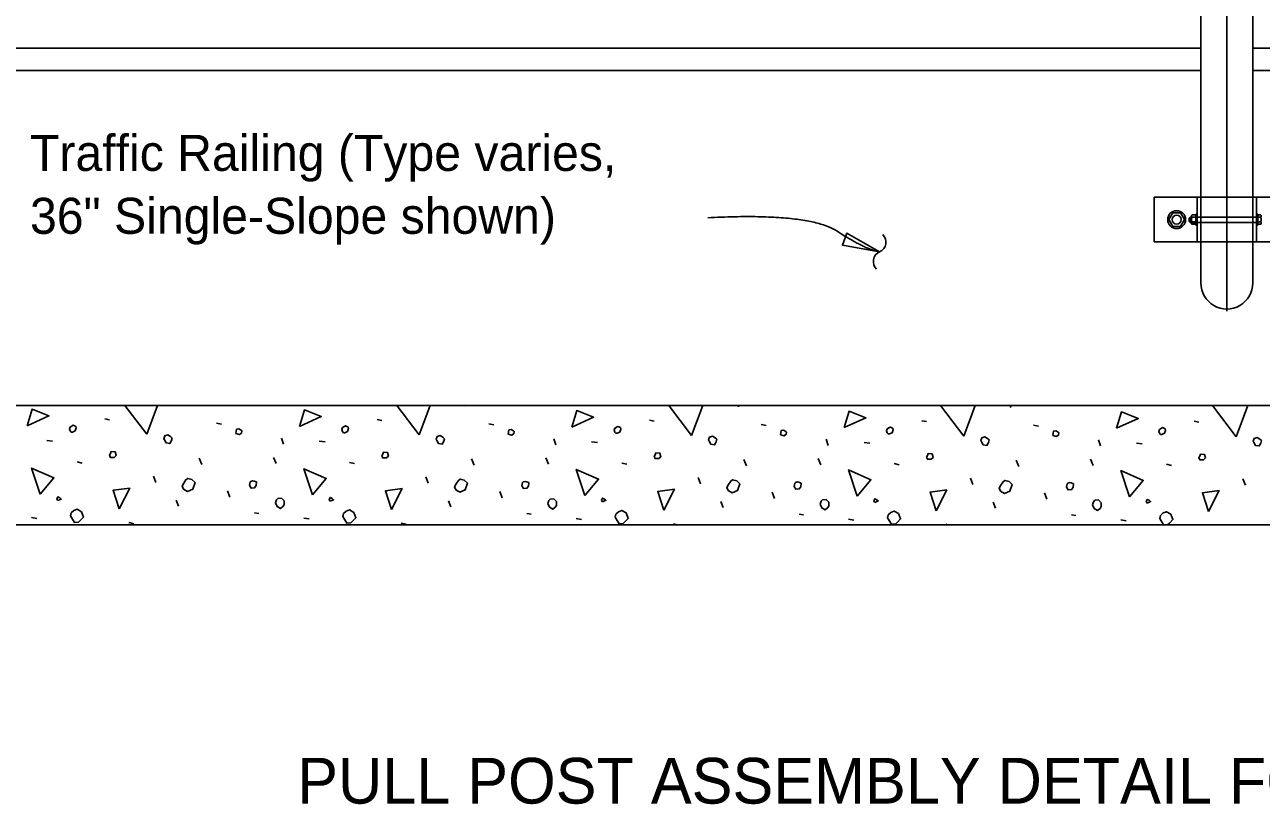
# Model space of a CAD drawing. Extents: x 0 to 72.1, y -7 to 30.
# Drawn here: x 5.5 to 12.41, y 13.96 to 18.32 of the extents above; entities that cross this region are included whole.
import ezdxf

# ---------------------------------------------------------------- set-up
doc = ezdxf.new("R2010")
doc.units = 0
for name, color, linetype in [('AdhocPoint_dp', 7, 'Continuous'), ('Border', 7, 'Continuous'), ('Patterning', 7, 'Continuous'), ('PlotBorder_dp', 7, 'Continuous'), ('SheetBorder_dp', 7, 'Continuous'), ('TextMisc', 7, 'Continuous'), ('TextStructures', 7, 'Continuous')]:
    doc.layers.add(name, color=color, linetype=linetype)

msp = doc.modelspace()

# ---------------------------------------------------------------- linework, layer by layer
at = {"layer": 'AdhocPoint_dp'}
for p, q in [((12.0147, 17.2229), (12.0147, 17.235)), ((12.0204, 17.2229), (12.0204, 17.235)), ((7.9664, 16.1864), (7.9651, 16.1899)), ((9.4903, 16.1829), (9.4877, 16.1899)), ((11.0141, 16.1793), (11.0102, 16.1899)), ((5.9441, 16.1157), (5.9706, 16.1104)), ((6.5699, 16.0909), (6.5964, 16.0856)), ((7.4679, 16.1122), (7.4945, 16.1068)), ((8.0937, 16.0874), (8.1202, 16.0821)), ((8.9918, 16.1086), (9.0183, 16.1033)), ((9.6175, 16.0839), (9.6441, 16.0786)), ((10.5156, 16.1051), (10.5421, 16.0998)), ((11.1414, 16.0803), (11.1679, 16.075)), ((12.0394, 16.1015), (12.0659, 16.0962)), ((5.6206, 15.9937), (5.6524, 15.9902)), ((6.9447, 15.9743), (6.9323, 16.0079)), ((7.1444, 15.9902), (7.1763, 15.9866)), ((8.4685, 15.9707), (8.4561, 16.0043)), ((8.6683, 15.9866), (8.7001, 15.9831)), ((9.9923, 15.9672), (9.9799, 16.0008)), ((10.1921, 15.9831), (10.2239, 15.9796)), ((11.5161, 15.9637), (11.5038, 15.9972)), ((11.7159, 15.9796), (11.7477, 15.976)), ((5.7886, 15.8753), (5.8168, 15.8682)), ((6.4868, 15.8594), (6.4727, 15.8947)), ((6.9023, 15.8647), (6.8881, 15.9)), ((7.3124, 15.8717), (7.3407, 15.8647)), ((8.0106, 15.8558), (7.9965, 15.8912)), ((8.4261, 15.8611), (8.4119, 15.8965)), ((8.8362, 15.8682), (8.8645, 15.8611)), ((9.5345, 15.8523), (9.5203, 15.8876)), ((9.9499, 15.8576), (9.9357, 15.8929)), ((10.36, 15.8647), (10.3883, 15.8576)), ((11.0583, 15.8488), (11.0441, 15.8841)), ((11.4737, 15.8541), (11.4596, 15.8894)), ((11.8838, 15.8611), (11.9121, 15.8541)), ((6.2305, 15.7586), (6.2164, 15.794)), ((7.7543, 15.7551), (7.7402, 15.7904)), ((9.2781, 15.7515), (9.264, 15.7869)), ((10.8019, 15.748), (10.7878, 15.7833)), ((12.3258, 15.7445), (12.3116, 15.7798)), ((6.6442, 15.6773), (6.63, 15.7126)), ((8.168, 15.6737), (8.1538, 15.7091)), ((6.356, 15.626), (6.3436, 15.6596)), ((7.8798, 15.6225), (7.8675, 15.6561)), ((9.4036, 15.6189), (9.3913, 15.6525)), ((9.6918, 15.6702), (9.6776, 15.7056)), ((10.9275, 15.6154), (10.9151, 15.649)), ((11.2156, 15.6667), (11.2015, 15.702)), ((6.782, 15.5889), (6.8068, 15.5854)), ((8.3059, 15.5854), (8.3306, 15.5818)), ((9.8297, 15.5818), (9.8544, 15.5783)), ((11.3535, 15.5783), (11.3782, 15.5748)), ((5.534, 15.5641), (5.5641, 15.5588)), ((6.0785, 15.5359), (6.1068, 15.5288)), ((7.0578, 15.5606), (7.0879, 15.5553)), ((7.6023, 15.5323), (7.6306, 15.5253)), ((8.5816, 15.5571), (8.6117, 15.5518)), ((9.1261, 15.5288), (9.1482, 15.5233)), ((10.1054, 15.5535), (10.1355, 15.5482)), ((10.6499, 15.5253), (10.6579, 15.5233)), ((11.6293, 15.55), (11.6593, 15.5447))]:
    msp.add_line(p, q, dxfattribs=at)
for points in [[(5.5093, 16.0768), (5.5375, 16.1687), (5.6312, 16.1316), (5.5093, 16.0768)], [(6.1792, 16.0291), (6.057, 16.1899)], [(6.2394, 16.1899), (6.1792, 16.0291)], [(7.0331, 16.0733), (7.0614, 16.1652), (7.155, 16.1281), (7.0331, 16.0733)], [(7.7031, 16.0255), (7.5781, 16.1899)], [(7.7645, 16.1899), (7.7031, 16.0255)], [(8.5569, 16.0697), (8.5852, 16.1617), (8.6789, 16.1245), (8.5569, 16.0697)], [(9.2269, 16.022), (9.0992, 16.1899)], [(9.2896, 16.1899), (9.2269, 16.022)], [(10.0807, 16.0662), (10.109, 16.1581), (10.2027, 16.121), (10.0807, 16.0662)], [(10.7507, 16.0185), (10.6204, 16.1899)], [(10.8148, 16.1899), (10.7507, 16.0185)], [(11.6045, 16.0627), (11.6328, 16.1546), (11.7265, 16.1175), (11.6045, 16.0627)], [(12.2745, 16.0149), (12.1415, 16.1899)], [(12.3399, 16.1899), (12.2745, 16.0149)], [(5.7567, 16.0414), (5.7638, 16.0414), (5.778, 16.0485), (5.7833, 16.0644), (5.7815, 16.0733), (5.7673, 16.0803), (5.7497, 16.0697), (5.7461, 16.0591), (5.7497, 16.0485), (5.7567, 16.0414)], [(6.6777, 16.0326), (6.6972, 16.0273), (6.7096, 16.0361), (6.7113, 16.0485), (6.7078, 16.052), (6.6937, 16.0591), (6.6813, 16.0574), (6.6795, 16.045), (6.6777, 16.0326)], [(7.2806, 16.0379), (7.2876, 16.0379), (7.3018, 16.045), (7.3071, 16.0609), (7.3053, 16.0697), (7.2912, 16.0768), (7.2735, 16.0662), (7.2699, 16.0556), (7.2735, 16.045), (7.2806, 16.0379)], [(8.2016, 16.0291), (8.221, 16.0238), (8.2334, 16.0326), (8.2351, 16.045), (8.2316, 16.0485), (8.2175, 16.0556), (8.2051, 16.0538), (8.2033, 16.0414), (8.2016, 16.0291)], [(8.8044, 16.0344), (8.8114, 16.0344), (8.8256, 16.0414), (8.8309, 16.0574), (8.8291, 16.0662), (8.815, 16.0733), (8.7973, 16.0627), (8.7938, 16.052), (8.7973, 16.0414), (8.8044, 16.0344)], [(9.7254, 16.0255), (9.7448, 16.0202), (9.7572, 16.0291), (9.759, 16.0414), (9.7554, 16.045), (9.7413, 16.052), (9.7289, 16.0503), (9.7271, 16.0379), (9.7254, 16.0255)], [(10.3282, 16.0308), (10.3353, 16.0308), (10.3494, 16.0379), (10.3547, 16.0538), (10.3529, 16.0627), (10.3388, 16.0697), (10.3211, 16.0591), (10.3176, 16.0485), (10.3211, 16.0379), (10.3282, 16.0308)], [(11.852, 16.0273), (11.8591, 16.0273), (11.8732, 16.0344), (11.8785, 16.0503), (11.8767, 16.0591), (11.8626, 16.0662), (11.8449, 16.0556), (11.8414, 16.045), (11.8449, 16.0344), (11.852, 16.0273)], [(6.2782, 15.9972), (6.2871, 15.9813), (6.3083, 15.9778), (6.3171, 15.9937), (6.3207, 16.0079), (6.3118, 16.0167), (6.2959, 16.0255), (6.28, 16.0202), (6.2747, 16.0043), (6.2782, 15.9972)], [(7.802, 15.9937), (7.8109, 15.9778), (7.8321, 15.9743), (7.8409, 15.9902), (7.8445, 16.0043), (7.8356, 16.0132), (7.8197, 16.022), (7.8038, 16.0167), (7.7985, 16.0008), (7.802, 15.9937)], [(9.3259, 15.9902), (9.3347, 15.9743), (9.3559, 15.9707), (9.3648, 15.9866), (9.3683, 16.0008), (9.3594, 16.0096), (9.3435, 16.0185), (9.3276, 16.0132), (9.3223, 15.9972), (9.3259, 15.9902)], [(10.8497, 15.9866), (10.8585, 15.9707), (10.8797, 15.9672), (10.8886, 15.9831), (10.8921, 15.9972), (10.8833, 16.0061), (10.8674, 16.0149), (10.8514, 16.0096), (10.8461, 15.9937), (10.8497, 15.9866)], [(11.2492, 16.022), (11.2686, 16.0167), (11.281, 16.0255), (11.2828, 16.0379), (11.2792, 16.0414), (11.2651, 16.0485), (11.2527, 16.0467), (11.251, 16.0344), (11.2492, 16.022)], [(12.3735, 15.9831), (12.3823, 15.9672), (12.4035, 15.9637), (12.4124, 15.9796), (12.4159, 15.9937), (12.4071, 16.0026), (12.3912, 16.0114), (12.3753, 16.0061), (12.37, 15.9902), (12.3735, 15.9831)], [(5.9759, 15.9), (5.9972, 15.9), (6.0078, 15.9106), (6.0025, 15.9301), (5.9795, 15.9318), (5.9759, 15.9212), (5.9706, 15.9124), (5.9759, 15.9), (5.9724, 15.9036)], [(7.4998, 15.8965), (7.521, 15.8965), (7.5316, 15.9071), (7.5263, 15.9265), (7.5033, 15.9283), (7.4998, 15.9177), (7.4945, 15.9089), (7.4998, 15.8965), (7.4962, 15.9)], [(9.0236, 15.8929), (9.0448, 15.8929), (9.0554, 15.9036), (9.0501, 15.923), (9.0271, 15.9248), (9.0236, 15.9142), (9.0183, 15.9053), (9.0236, 15.8929), (9.02, 15.8965)], [(10.5474, 15.8894), (10.5686, 15.8894), (10.5792, 15.9), (10.5739, 15.9195), (10.5509, 15.9212), (10.5474, 15.9106), (10.5421, 15.9018), (10.5474, 15.8894), (10.5439, 15.8929)], [(12.0712, 15.8859), (12.0924, 15.8859), (12.103, 15.8965), (12.0977, 15.9159), (12.0747, 15.9177), (12.0712, 15.9071), (12.0659, 15.8983), (12.0712, 15.8859), (12.0677, 15.8894)], [(5.5817, 15.6932), (5.534, 15.8399), (5.6595, 15.7851), (5.5817, 15.6932)], [(6.3843, 15.7215), (6.4073, 15.7091), (6.4373, 15.7215), (6.4497, 15.7586), (6.432, 15.7763), (6.409, 15.7816), (6.3984, 15.7745), (6.3861, 15.7551), (6.3772, 15.7392), (6.3843, 15.7215)], [(7.1055, 15.6897), (7.0578, 15.8364), (7.1833, 15.7816), (7.1055, 15.6897)], [(7.9081, 15.7179), (7.9311, 15.7056), (7.9611, 15.7179), (7.9735, 15.7551), (7.9558, 15.7727), (7.9329, 15.778), (7.9223, 15.771), (7.9099, 15.7515), (7.901, 15.7356), (7.9081, 15.7179)], [(8.6294, 15.6861), (8.5816, 15.8328), (8.7071, 15.778), (8.6294, 15.6861)], [(10.1532, 15.6826), (10.1054, 15.8293), (10.231, 15.7745), (10.1532, 15.6826)], [(11.677, 15.679), (11.6293, 15.8258), (11.7548, 15.771), (11.677, 15.679)], [(6.0237, 15.6119), (5.9901, 15.7162), (6.0838, 15.7285), (6.0237, 15.6119)], [(6.7538, 15.7445), (6.7626, 15.7285), (6.782, 15.7303), (6.7909, 15.7427), (6.7927, 15.7621), (6.7803, 15.7674), (6.7714, 15.7692), (6.7608, 15.7657), (6.7573, 15.7621), (6.7538, 15.7445)], [(7.5475, 15.6083), (7.5139, 15.7126), (7.6076, 15.725), (7.5475, 15.6083)], [(8.2776, 15.7409), (8.2864, 15.725), (8.3059, 15.7268), (8.3147, 15.7392), (8.3165, 15.7586), (8.3041, 15.7639), (8.2953, 15.7657), (8.2846, 15.7621), (8.2811, 15.7586), (8.2776, 15.7409)], [(9.0713, 15.6048), (9.0377, 15.7091), (9.1314, 15.7215), (9.0713, 15.6048)], [(9.4319, 15.7144), (9.4549, 15.702), (9.485, 15.7144), (9.4973, 15.7515), (9.4797, 15.7692), (9.4567, 15.7745), (9.4461, 15.7674), (9.4337, 15.748), (9.4249, 15.7321), (9.4319, 15.7144)], [(9.8014, 15.7374), (9.8102, 15.7215), (9.8297, 15.7232), (9.8385, 15.7356), (9.8403, 15.7551), (9.8279, 15.7604), (9.8191, 15.7621), (9.8085, 15.7586), (9.8049, 15.7551), (9.8014, 15.7374)], [(10.5951, 15.6013), (10.5615, 15.7056), (10.6552, 15.7179), (10.5951, 15.6013)], [(10.9557, 15.7109), (10.9787, 15.6985), (11.0088, 15.7109), (11.0211, 15.748), (11.0035, 15.7657), (10.9805, 15.771), (10.9699, 15.7639), (10.9575, 15.7445), (10.9487, 15.7285), (10.9557, 15.7109)], [(11.3252, 15.7339), (11.334, 15.7179), (11.3535, 15.7197), (11.3623, 15.7321), (11.3641, 15.7515), (11.3517, 15.7568), (11.3429, 15.7586), (11.3323, 15.7551), (11.3287, 15.7515), (11.3252, 15.7339)], [(12.1189, 15.5977), (12.0853, 15.702), (12.179, 15.7144), (12.1189, 15.5977)], [(5.6807, 15.6578), (5.7002, 15.6667), (5.6931, 15.6737), (5.6807, 15.679), (5.6754, 15.6667), (5.6807, 15.6578)], [(6.8987, 15.6455), (6.9093, 15.6242), (6.927, 15.6136), (6.9411, 15.6242), (6.9482, 15.6349), (6.9482, 15.6561), (6.9323, 15.672), (6.9129, 15.6702), (6.904, 15.6614), (6.8987, 15.6455)], [(7.2045, 15.6543), (7.224, 15.6631), (7.2169, 15.6702), (7.2045, 15.6755), (7.1992, 15.6631), (7.2045, 15.6543)], [(8.4225, 15.6419), (8.4331, 15.6207), (8.4508, 15.6101), (8.465, 15.6207), (8.472, 15.6313), (8.472, 15.6525), (8.4561, 15.6684), (8.4367, 15.6667), (8.4278, 15.6578), (8.4225, 15.6419)], [(8.7284, 15.6508), (8.7478, 15.6596), (8.7407, 15.6667), (8.7284, 15.672), (8.7231, 15.6596), (8.7284, 15.6508)], [(9.9463, 15.6384), (9.957, 15.6172), (9.9746, 15.6066), (9.9888, 15.6172), (9.9958, 15.6278), (9.9958, 15.649), (9.9799, 15.6649), (9.9605, 15.6631), (9.9517, 15.6543), (9.9463, 15.6384)], [(10.2522, 15.6472), (10.2716, 15.6561), (10.2645, 15.6631), (10.2522, 15.6684), (10.2469, 15.6561), (10.2522, 15.6472)], [(11.4702, 15.6349), (11.4808, 15.6136), (11.4984, 15.603), (11.5126, 15.6136), (11.5197, 15.6242), (11.5197, 15.6455), (11.5038, 15.6614), (11.4843, 15.6596), (11.4755, 15.6508), (11.4702, 15.6349)], [(11.776, 15.6437), (11.7954, 15.6525), (11.7884, 15.6596), (11.776, 15.6649), (11.7707, 15.6525), (11.776, 15.6437)], [(5.7514, 15.573), (5.7744, 15.5359), (5.7974, 15.5376), (5.8062, 15.5465), (5.8257, 15.5659), (5.8133, 15.596), (5.7886, 15.6101), (5.7709, 15.603), (5.7567, 15.5889), (5.7514, 15.573)], [(7.2753, 15.5694), (7.2982, 15.5323), (7.3212, 15.5341), (7.3301, 15.5429), (7.3495, 15.5624), (7.3371, 15.5924), (7.3124, 15.6066), (7.2947, 15.5995), (7.2806, 15.5854), (7.2753, 15.5694)], [(8.7991, 15.5659), (8.822, 15.5288), (8.845, 15.5306), (8.8539, 15.5394), (8.8733, 15.5588), (8.8609, 15.5889), (8.8362, 15.603), (8.8185, 15.596), (8.8044, 15.5818), (8.7991, 15.5659)], [(10.3229, 15.5624), (10.3459, 15.5253), (10.3688, 15.527), (10.3777, 15.5359), (10.3971, 15.5553), (10.3848, 15.5854), (10.36, 15.5995), (10.3423, 15.5924), (10.3282, 15.5783), (10.3229, 15.5624)], [(11.8898, 15.5233), (11.8927, 15.5235), (11.9015, 15.5323), (11.9209, 15.5518), (11.9086, 15.5818), (11.8838, 15.596), (11.8661, 15.5889), (11.852, 15.5748), (11.8467, 15.5588)], [(6.5728, 15.5233), (6.5717, 15.5235), (6.5702, 15.5233)], [(11.8467, 15.5588), (11.8687, 15.5233)]]:
    msp.add_lwpolyline(points, dxfattribs=at)
at = {"layer": 'Border'}
msp.add_lwpolyline([(10.2794, 17.0491), (10.0958, 17.1535), (10.0717, 17.0873)], close=True, dxfattribs=at)
for centre, start, end in [((10.2552, 17.1041), 294.14658, 45.87379), ((10.304, 16.9954), 114.14657, 225.87379)]:
    msp.add_arc(centre, 0.0596, start, end, dxfattribs=at)
msp.add_open_spline([(9.3188, 17.2407), (9.8816, 17.2691), (10.203, 17.0609), (10.2796, 17.0497)], degree=2, dxfattribs=at)
at = {"layer": 'Patterning'}
for p, q in [((12.0764, 17.3548), (12.0764, 17.1048)), ((12.3681, 17.3548), (12.3681, 17.1048)), ((12.3889, 17.2444), (12.024, 17.2444)), ((12.024, 17.2145), (12.3889, 17.2145))]:
    msp.add_line(p, q, dxfattribs=at)
at = {"layer": 'PlotBorder_dp'}
for p, q in [((12.0764, 18.6048), (12.0764, 17.3548)), ((12.3681, 18.6048), (12.3681, 17.3548)), ((11.8163, 17.3548), (12.6282, 17.3548)), ((11.8163, 17.1048), (11.8163, 17.3548)), ((12.0556, 17.3548), (12.0556, 17.1048)), ((12.3889, 17.3548), (12.3889, 17.1048)), ((12.0118, 17.2378), (12.0175, 17.2444)), ((12.0118, 17.2201), (12.0118, 17.2378)), ((12.0175, 17.2444), (12.024, 17.2444)), ((12.0175, 17.2145), (12.0175, 17.2444)), ((12.024, 17.2477), (12.024, 17.212)), ((12.0287, 17.2428), (12.049, 17.2428)), ((12.0289, 17.2558), (12.049, 17.2558)), ((12.049, 17.2601), (12.049, 17.1995)), ((12.049, 17.2601), (12.0556, 17.2601)), ((12.049, 17.2558), (12.049, 17.2039)), ((12.3952, 17.2601), (12.3891, 17.2601)), ((12.3952, 17.2601), (12.3952, 17.1995)), ((12.4099, 17.2558), (12.3952, 17.2558)), ((12.41, 17.2428), (12.3952, 17.2428)), ((12.0118, 17.2201), (12.0175, 17.2145)), ((12.0175, 17.2145), (12.024, 17.2145)), ((12.0287, 17.2169), (12.049, 17.2169)), ((12.029, 17.2039), (12.049, 17.2039)), ((12.049, 17.1995), (12.0556, 17.1995)), ((12.3952, 17.1995), (12.3891, 17.1995)), ((12.41, 17.2168), (12.3952, 17.2168)), ((12.4099, 17.2038), (12.3952, 17.2038)), ((12.6282, 17.1048), (11.8163, 17.1048)), ((12.0763, 17.1048), (12.0763, 16.8757)), ((12.368, 16.8757), (12.368, 17.1048))]:
    msp.add_line(p, q, dxfattribs=at)
msp.add_lwpolyline([(11.9196, 17.2674), (11.9629, 17.2674), (11.9846, 17.2298), (11.9629, 17.1923), (11.9196, 17.1923), (11.8979, 17.2298)], close=True, dxfattribs=at)
for radius in [0.05, 0.025]:
    msp.add_circle((11.9413, 17.2298), radius, dxfattribs=at)
for centre, radius, start, end in [((12.0306, 17.2493), 0.00674, 104.48908, 254.18889), ((12.0435, 17.2298), 0.0196, 138.62797, 221.37203), ((12.4082, 17.2493), 0.00673, 285.7823, 75.54039), ((12.3953, 17.2298), 0.0196, 318.62797, 41.37203), ((12.0306, 17.2104), 0.00673, 105.7823, 255.54039), ((12.4082, 17.2104), 0.00674, 284.48908, 74.18889)]:
    msp.add_arc(centre, radius, start, end, dxfattribs=at)
msp.add_ellipse((12.2222, 16.8757), major_axis=(0, 0.1458), ratio=0.999499, start_param=1.570796, end_param=4.712389, dxfattribs=at)
at = {"layer": 'SheetBorder_dp'}
msp.add_line((12.2222, 26.6864), (12.2222, 16.7178), dxfattribs=at)
at = {"layer": 'TextMisc'}
for p, q in [((2.368, 18.1899), (12.0764, 18.1899)), ((12.3681, 18.1899), (22.0764, 18.1899)), ((2.368, 18.0649), (12.0764, 18.0649)), ((12.3681, 18.0649), (22.0764, 18.0649)), ((0.8353, 16.1899), (23.6092, 16.1899)), ((0.8353, 15.5233), (23.6092, 15.5233))]:
    msp.add_line(p, q, dxfattribs=at)

# ---------------------------------------------------------------- texts
at = {"layer": 'Border'}
for s, p in [('Traffic Railing (Type varies,', (5.5255, 17.5025)), ('36" Single-Slope shown)', (5.5255, 17.1505))]:
    msp.add_text(s, height=0.2016, dxfattribs=at).set_placement(p)
at = {"layer": 'TextStructures'}
msp.add_text('PULL POST ASSEMBLY DETAIL FOR TRAFFIC RAILING', height=0.256001, dxfattribs=at).set_placement((7.0209, 13.9629))

doc.saveas('drawing.dxf')
